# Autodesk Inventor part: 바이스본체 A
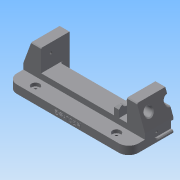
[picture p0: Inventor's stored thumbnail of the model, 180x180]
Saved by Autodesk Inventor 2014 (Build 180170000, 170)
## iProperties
Created: 2017-04
Part Number: 바이스본체 A
Material: 알루미늄 6061
Document SubType Name: Modeling
Designer: mduedu
Density: 2.71 g/cm^3
Appearance: 기본값
Mass: 324.199 g
Surface Area: 276.734 cm^2
Volume: 119.631 cm^3
Author: mduedu
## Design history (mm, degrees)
sketch "스케치1"
  geometry: L1 (-75, 0)-(75, 0); L2 (-75, 0)-(-75, 17); L3 (-53, 17)-(53, 17); L4 (75, 17)-(75, 0); L5 (-75, 17)-(-65.173, 44); L6 (-65.173, 44)-(-53, 44); L7 (-53, 44)-(-53, 17); L8 (0, 0)-(0, 17); L9 (75, 17)-(65.173, 44); L10 (65.173, 44)-(53, 44); L11 (53, 44)-(53, 17); 1 further point
  constraints: 22 end point, 4 perpendicular, 2 horizontal alignment, 2 midpoint, 2 symmetric about line, 1 coincident, 1 collinear, 1 horizontal, 1 vertical
  dimensions: "d0" = 150 distance of L1.start L1.end; "d1" = 17 distance of L1.start L2.end; "d2" = 27 distance of L3.start L6.end; "d3" = 22 distance of L3.start L2.end; "d4" = 70 deg angle of L3 L5; "d54" = 20 deg angle of L9 L4
extrude "돌출1" new body sketch "스케치1" stored distance "d5" = 70; taper "d6" = 0 deg
sketch "스케치2"
  geometry: L1 (0, 70)-(106, 70) reference; L2 (106, 70)-(106, 0) reference; L3 (106, 0)-(0, 0) reference; L4 (0, 47)-(106, 47); L5 (106, 47)-(106, 23); L6 (106, 23)-(0, 23); L7 (0, 23)-(0, 47); L8 (0, 70)-(0, 0) reference; 2 further points
  constraints: 8 end point, 2 parallel, 2 point on line, 1 horizontal, 1 horizontal alignment, 1 midpoint, 1 perpendicular
  dimensions: "d7" = 24 distance between parallel lines of L6 L4
extrude "돌출2" cut sketch "스케치2" stored distance "d9" = 70; taper "d10" = 0 deg
sketch "스케치3"
  geometry: L1 (22, -23)-(128, -23) reference; L2 (128, -47)-(22, -47) reference; L3 (22, -18)-(128, -18); L4 (128, -52)-(22, -52); L5 (22, -18)-(22, -52); L6 (128, -18)-(128, -52); 1 further point
  constraints: 8 end point, 3 parallel, 2 point on line, 1 perpendicular
  dimensions: "d11" = 5 distance between parallel lines of L3 L1; "d12" = 5 distance between parallel lines of L4 L2
extrude "돌출3" cut sketch "스케치3" distance "d13" = 12; taper "d14" = 0 deg
fillet "모깎기1" dims "d15" = 3, "d16" = 3
sketch "스케치4"
  geometry: L1 (103, 23)-(3, 23) reference; L2 (0, 26)-(0, 0) reference; L3 (106, 0)-(0, 0) reference; L4 (106, 26)-(106, 0) reference; L5 (96, 0)-(90, 0); L6 (90, 0)-(90, 19.5); L7 (96, 19.5)-(96, 0); L8 (90, 19.5)-(96, 19.5); A1 r 3 centre (3, 26) between (0, 26) and (3, 23) reference; A2 r 3 centre (103, 26) between (103, 23) and (106, 26) reference; 1 further point
  constraints: 8 end point, 2 perpendicular, 1 horizontal, 1 parallel, 1 point on line
  dimensions: "d17" = 10 distance between parallel lines of L7 L4; "d18" = 6 distance between parallel lines of L7 L6; "d27" = 3.5 distance between parallel lines of L8 L1
extrude "돌출4" join sketch "스케치4" distance "d19" = 12; taper "d20" = 0 deg
chamfer "모따기1" distance "d21" = 3; stored, may be unused: second distance "d22" = 2, angle "d23" = 45 deg
chamfer "모따기2" distance "d24" = 3; stored, may be unused: second distance "d25" = 2, angle "d26" = 45 deg
sketch "스케치5"
  geometry: L1 (-15.5, 35.8)-(-15.5, -25.8) reference; L2 (19.5, 0)-(0, 0) reference; C1 r 6.5 at (9.5, 15); 1 further point
  constraints: 1 centre point
  dimensions: "d28" = 13 diameter of C1; "d30" = 15 distance from line of C1.centre L2; "d31" = 25 distance from line of C1.centre L1
extrude "돌출5" cut sketch "스케치5" stored distance "d32" = 12; taper "d33" = 0 deg
sketch "스케치6"
  geometry: C1 r 5 at (-10, 15); C2 r 5 at (-60, 15); A1 r 6.5 centre (-10, 15) between (-15.766, 12) and (-4.234, 12) reference; A2 r 6.5 centre (-60, 15) between (-65.766, 12) and (-54.234, 12) reference; 1 further point
  constraints: 2 centre point, 2 coincident
  dimensions: "d34" = 10 diameter of C1; "d35" = 10 diameter of C2 (= d34)
extrude "돌출6" cut sketch "스케치6" stored distance "d36" = 12; taper "d37" = 0 deg
chamfer "모따기3" distance "d38" = 1; stored, may be unused: second distance "d39" = 2, angle "d40" = 45 deg
chamfer "모따기4" distance "d41" = 1; stored, may be unused: second distance "d42" = 2, angle "d43" = 45 deg
sketch "스케치7"
  geometry: L1 (-35, 35.8)-(-35, -25.8) reference; L2 (-70, 0)-(0, 0) reference; C1 r 5 at (-35, 15); 1 further point
  constraints: 1 centre point, 1 point on line
  dimensions: "d44" = 10 diameter of C1; "d45" = 15 distance from line of C1.centre L2
extrude "돌출7" cut sketch "스케치7" stored distance "d46" = 12; taper "d47" = 0 deg
chamfer "모따기5" distance "d48" = 1; stored, may be unused: second distance "d49" = 2, angle "d50" = 45 deg
node "작업축1"
sketch "스케치8"
  geometry: L1 (-105, 32)-(105, 32) reference; L2 (58, 32)-(64, 32); L3 (64, 32)-(64, 40); L4 (64, 40)-(58, 40); L5 (58, 40)-(58, 32); L6 (53, 38)-(53, 26) reference; 1 further point
  constraints: 8 end point, 2 parallel, 1 horizontal, 1 perpendicular, 1 point on line
  dimensions: "d51" = 5 distance from line of L6 L2.start; "d52" = 6 distance of L3.end L4.end; "d53" = 16 diameter of L4 L1
revolve "회전1" sketch "스케치8" stored, may be unused: angle "d55" = 90 deg
fillet "모깎기2"
chamfer "모따기6" distance "d56" = 1; stored, may be unused: second distance "d57" = 2, angle "d58" = 45 deg
sketch "스케치9"
  geometry: L1 (17.5, 3)-(52.5, 3); L2 (52.5, 13)-(17.5, 13); L3 (70, 0)-(0, 0) reference; L4 (17.5, 8)-(52.5, 8); A1 r 5 centre (17.5, 8) between (17.5, 13) and (17.5, 3); A2 r 5 centre (52.5, 8) between (52.5, 3) and (52.5, 13); 3 further points
  constraints: 6 end point, 4 point on circle, 3 tangent, 2 centre point, 2 midpoint, 2 parallel, 1 horizontal, 1 vertical alignment
  dimensions: "d59" = 35 distance of L4.start L4.end; "d61" = 5 radius of A2; "d62" = 8 distance between parallel lines of L3 L4
extrude "돌출8" cut sketch "스케치9" distance "d63" = 3; taper "d64" = 0 deg
chamfer "모따기7" distance "d65" = 1; stored, may be unused: second distance "d66" = 2, angle "d67" = 45 deg
chamfer "모따기8" distance "d68" = 1; stored, may be unused: second distance "d69" = 2, angle "d70" = 45 deg
feature "분할1"
sketch "스케치10"
  geometry: L1 (35, 27)-(0, 27) reference; L2 (0, 0)-(0, 27) reference; 1 further point
  dimensions: "d85" = 11.5 distance from line of point (12, 15.5) L1; "d86" = 12 distance from line of point (12, 15.5) L2
hole "구멍1" sketch "스케치10" at (12, 15.5) diameter "d71" = 3.242; stored, may be unused: countersink angle "d75" = 90 deg, drill point angle "d77" = 120 deg; dims "d72" = 6, "d73" = 4, "d74" = 2, "d76" = 8
sketch "스케치11"
  geometry: A1 r 5 centre (17.5, 8) between (17.5, 13) and (17.5, 3) reference; 1 further point
  constraints: 1 coincident
hole "구멍3" sketch "스케치11" at (17.5, 8) diameter "d78" = 2.459; stored, may be unused: countersink angle "d82" = 90 deg, drill point angle "d84" = 120 deg; dims "d79" = 4.5, "d80" = 4, "d81" = 2, "d83" = 6
sketch "스케치13"
  geometry: L1 (75, 0)-(75, 35) reference; L2 (-75, 0)-(-75, 35) reference; L3 (-75, 35)-(75, 35); L4 (75, 35)-(75, 55); L5 (75, 55)-(-75, 55); L6 (-75, 55)-(-75, 35); 1 further point
  constraints: 8 end point, 2 parallel, 1 horizontal, 1 perpendicular, 1 point on line
  dimensions: "d90" = 20 distance between parallel lines of L5 L3; "d94" = 150 distance of L4.end L5.end (derived)
extrude "돌출9" join sketch "스케치13" distance "d92" = 10; taper "d93" = 0 deg
sketch "스케치14"
  geometry: L1 (-75, -35)-(-75, -55) reference; L2 (75, -55)-(75, -35) reference; L3 (-75, -45)-(75, -45); 3 further points
  constraints: 2 end point, 2 midpoint, 2 point on line
  dimensions: "d95" = 50 horizontal distance of point (-50, -45) point (0, 0); "d96" = 100 distance of point (50, -45) point (-50, -45)
fillet "모깎기3" dims "d97" = 12
chamfer "모따기9" distance "d98" = 1; stored, may be unused: second distance "d99" = 2, angle "d100" = 45 deg
hole "구멍4" sketch "스케치14" diameter "d101" = 4.134; stored, may be unused: countersink angle "d105" = 90 deg, drill point angle "d107" = 118 deg; dims "d102" = 6, "d103" = 10, "d104" = 4, "d106" = 8
sketch "스케치15"
  geometry: L1 (0, 0)-(126, 0) reference; 3 further points
  constraints: 1 midpoint, 1 vertical alignment, 1 other
  dimensions: "d109" = 5 distance from line of point (63, 5) L1
feature "엠보싱2" sketch "스케치15" dims "d0" = 150, "d1" = 17, "d2" = 27, "d3" = 22, "d4" = 70 deg, "d54" = 20 deg, "d110" = 0.5, "d111" = 0
node "솔리드1"
mirror "대칭1"
mirror "대칭2"
mirror "대칭3"
mirror "대칭4"
node "투영된 루프1"
